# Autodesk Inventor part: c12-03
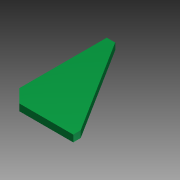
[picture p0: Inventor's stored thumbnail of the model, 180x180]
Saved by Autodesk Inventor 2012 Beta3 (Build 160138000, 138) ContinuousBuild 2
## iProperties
Created: 2011-01
Part Number: c12-03
Material: Default
Document SubType Name: Modeling
Designer: Beta-8540w
Density: 1 g/cm^3
Author: Beta-8540w
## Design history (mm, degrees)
sketch "Sketch1"
  geometry: L1 (0, 0)-(0, 120); L2 (10, 120)-(80, 8.885); L3 (80, 0)-(0, 0); L4 (16, 0)-(0, 16); L5 (10, 120)-(0, 120); L6 (80, 8.885)-(80, 0)
  constraints: 12 end point, 3 perpendicular, 2 point on line, 1 vertical
  dimensions: "d2" = 16 distance of L4.start L1.start; "d3" = 45 deg angle of L3 L4; "d6" = 120 distance between parallel lines of L5 L3; "d7" = 10 distance of L2.start L1.end; "d8" = 80 distance of L3.start L1.start
extrude "Extrusion1" new body sketch "Sketch1" stored distance "d4" = 8; taper "d5" = 0 deg
body "Solid1"
